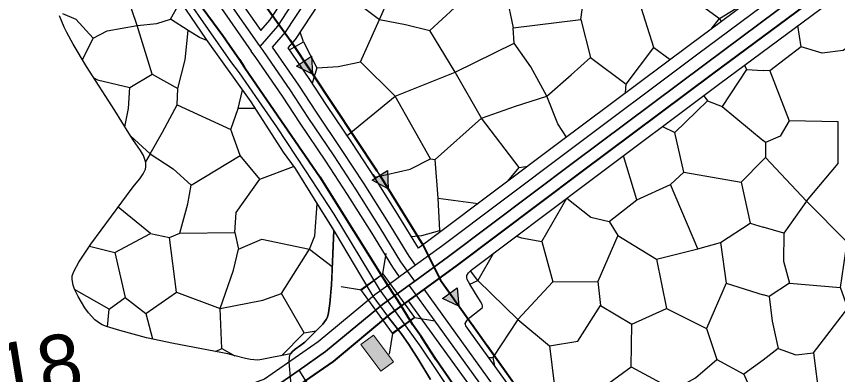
# Model space of a CAD drawing. Extents: x -64005 to -55000, y -89025 to -80000.
# Drawn here: x -62111 to -61273, y -80924 to -80558 of the extents above; entities that cross this region are included whole.
import ezdxf
from ezdxf.enums import TextEntityAlignment as Align

# ---------------------------------------------------------------- set-up
doc = ezdxf.new("R2010")
doc.units = 0
doc.header["$LTSCALE"] = 32
for name, pattern in [('DASH_DOUBLE_DOT', [9.2, 5, -1.2, 0.3, -1.2, 0.3, -1.2]), ('DOT_DASHED', [7.7, 5, -1.2, 0.3, -1.2]), ('LONG_DASHED', [7.5, 6, -1.5])]:
    doc.linetypes.add(name, pattern=pattern)
for name, color, linetype, lineweight in [('18', 7, 'Continuous', 25), ('19', 7, 'Continuous', 25), ('20', 7, 'Continuous', 25), ('3', 7, 'Continuous', 25), ('39', 7, 'LONG_DASHED', 25), ('5', 7, 'Continuous', 40), ('53', 7, 'DASH_DOUBLE_DOT', 25), ('63', 7, 'DASH_DOUBLE_DOT', 25), ('7', 7, 'Continuous', 13), ('8', 7, 'Continuous', 25)]:
    doc.layers.add(name, color=color, linetype=linetype, lineweight=lineweight)
doc.layers.add('30', color=7, linetype='Continuous')

msp = doc.modelspace()

# ---------------------------------------------------------------- hatches: boundary and pattern name
at = {"layer": '18'}
for points in [[(-61809.8, -80598.75), (-61808.66, -80617.22), (-61825.22, -80608.97)], [(-61732.29, -80715.66), (-61731.68, -80734.14), (-61747.99, -80725.43)], [(-61661.08, -80835.3), (-61659.3, -80853.71), (-61676.13, -80846.05)]]:
    msp.add_hatch(color=256, dxfattribs=at).paths.add_polyline_path(points)
at = {"layer": '7'}
msp.add_hatch(color=256, dxfattribs=at).paths.add_polyline_path([(-61726.19, -80910.68), (-61746.45, -80883.37), (-61759.3, -80892.9), (-61739.05, -80920.21)])

# ---------------------------------------------------------------- linework, layer by layer
at = {"layer": '18'}
for p, q in [((-61781.03, -80658.89), (-61740.16, -80720.55)), ((-61630.24, -80894.41), (-61587.26, -80954.62))]:
    msp.add_line(p, q, dxfattribs=at)
at = {"layer": '18', "linetype": 'DOT_DASHED', "lineweight": 40}
msp.add_lwpolyline([(-62130.95, -80220.51), (-62065.47, -80292.93), (-61983.02, -80390.5), (-61893.31, -80496.28), (-61831.59, -80582.62), (-61739.82, -80721.06), (-61696.2, -80791.15), (-61678.11, -80827.36), (-61574.26, -80972.82), (-61474.5, -81109.75), (-61380.53, -81246.93), (-61313.48, -81342.67)], dxfattribs=at)
at = {"layer": '18'}
for points in [[(-61859.79, -80543.17), (-61831.59, -80582.62), (-61817.51, -80603.86)], [(-61705.26, -80776.6), (-61696.2, -80791.15), (-61678.11, -80827.36), (-61668.6, -80840.67)]]:
    msp.add_lwpolyline(points, dxfattribs=at)
for points in [[(-61809.8, -80598.75), (-61808.66, -80617.22), (-61825.22, -80608.97)], [(-61732.29, -80715.66), (-61731.68, -80734.14), (-61747.99, -80725.43)], [(-61661.08, -80835.3), (-61659.3, -80853.71), (-61676.13, -80846.05)]]:
    msp.add_lwpolyline(points, close=True, dxfattribs=at)
for centre in [(-61794.84, -80638.05), (-61718.47, -80755.37), (-61644.77, -80874.06)]:
    msp.add_circle(centre, 0.5, dxfattribs=at)
at = {"layer": '19'}
for p, q in [((-61402.12, -80571.2), (-61393.6, -80560.36)), ((-61393.6, -80560.36), (-61391.78, -80563.51)), ((-62043.53, -80602.67), (-62032.51, -80580.63)), ((-61460.64, -80590.12), (-61443.7, -80602.22)), ((-61489.25, -80636.31), (-61488.59, -80627.42)), ((-61773.54, -80679.96), (-61724.57, -80639.78)), ((-61867.15, -80652.36), (-61884.61, -80652.12)), ((-61974.45, -80698.38), (-61979.12, -80706.61)), ((-61346.47, -80702.34), (-61348.89, -80704.76)), ((-61862.61, -80724.38), (-61828.26, -80711.29)), ((-61597.75, -80712.48), (-61589.06, -80711.09)), ((-61745.21, -80722.95), (-61744.82, -80722.18)), ((-61680.53, -80743.76), (-61639.59, -80749.05)), ((-61677.97, -80777.88), (-61678.78, -80776.81)), ((-61648.31, -80831.34), (-61640.06, -80827.78)), ((-62016.38, -80856.84), (-62051.49, -80836.9)), ((-61978.76, -80861.25), (-61972.03, -80887.33)), ((-61817.14, -80881.08), (-61805.12, -80879.09)), ((-61901.25, -80896.94), (-61888.17, -80904.37)), ((-61629.09, -80906.37), (-61624.64, -80906.19))]:
    msp.add_line(p, q, dxfattribs=at)
for points in [[(-60656, -80058.71), (-60736.07, -80110.4), (-60829.56, -80171.35), (-60995.24, -80276.06), (-61089.62, -80335.36), (-61146.26, -80375.39), (-61228.6, -80439.09), (-61304.45, -80498.56), (-61423.15, -80586.84), (-61557.42, -80687.33), (-61684.72, -80782.95), (-61700.7, -80794.56)], [(-62451.82, -80075.02), (-62421.27, -80077.57), (-62404.53, -80079.71), (-62388.83, -80081.51), (-62362.81, -80088.69), (-62340.82, -80101.26), (-62317.5, -80116.52), (-62297.31, -80135.37), (-62269.04, -80160.92), (-62205.35, -80231.41), (-62145.24, -80301.62), (-62103.48, -80350.87), (-62044.29, -80419.34), (-61992.7, -80480.96), (-61964.43, -80514.17), (-61943.35, -80543.35), (-61917.33, -80581.95), (-61871.66, -80645.3), (-61838.76, -80696.8), (-61826.6, -80713.58), (-61806.97, -80744.83), (-61787.11, -80776.61)], [(-61833.68, -80590.41), (-61826.2, -80581.78), (-61793.4, -80531.79), (-61776.09, -80505.2), (-61766.99, -80481.49), (-61758.32, -80447.6), (-61747.16, -80415.22), (-61715.39, -80338.74), (-61687.94, -80245.45), (-61669.19, -80193.12), (-61660.33, -80161.85), (-61656.91, -80133.65)], [(-61646.85, -80817.07), (-61527.41, -80727.33), (-61393.27, -80626.92), (-61274.09, -80538.32), (-61197.88, -80478.53), (-61116.54, -80415.58), (-61061.89, -80377), (-60968.59, -80318.37), (-60881, -80263.01)], [(-61784.83, -80525.57), (-61770.63, -80538.44), (-61740.44, -80561.54), (-61717.36, -80509.13), (-61740.88, -80470.05)], [(-61740.44, -80561.54), (-61713.8, -80566.43), (-61688.94, -80572.65), (-61651.21, -80537.55), (-61680.06, -80497.13), (-61717.36, -80509.13)], [(-61611.26, -80535.78), (-61604.16, -80569.97), (-61534.9, -80561.53), (-61530.46, -80529.1), (-61532.69, -80496.25)], [(-62064.02, -80555.31), (-62050.27, -80561.1), (-62032.51, -80580.63), (-62018.31, -80573.09), (-61987.69, -80567.76), (-62004.1, -80519.35)], [(-61444.34, -80523.32), (-61393.6, -80560.36), (-61357.4, -80537.94)], [(-61534.9, -80561.53), (-61524.98, -80600.32), (-61488.59, -80627.42), (-61460.64, -80590.12), (-61479.39, -80529.55)], [(-61987.69, -80567.76), (-61967.71, -80565.54), (-61953.5, -80561.1), (-61943.55, -80543.08)], [(-62053.84, -80822.93), (-62053.44, -80821.13), (-62052.41, -80818.56), (-62047.09, -80809.03), (-62043.22, -80802.74), (-62034.88, -80790.5), (-61992.81, -80733.51), (-61990.37, -80730.33), (-61985.12, -80723.91), (-61981.65, -80719.03), (-61979.32, -80714.09), (-61978.79, -80711.6), (-61978.86, -80707.88), (-61979.38, -80705.37), (-61981.34, -80700.3), (-61984.24, -80695.2), (-61991.32, -80684.98), (-61996.32, -80677.41), (-62010.47, -80654.39), (-62039.47, -80609.48), (-62053.09, -80586.61), (-62059.41, -80574.85), (-62062.15, -80569.23), (-62066.96, -80557.72)], [(-61916.53, -80583.06), (-61924.2, -80579.75), (-61935.75, -80572.65), (-61953.5, -80561.1)], [(-61804.48, -80610.7), (-61782.7, -80609.39), (-61759.79, -80604.54), (-61740.44, -80561.54)], [(-61243.06, -80576.2), (-61267.46, -80593.07), (-61288.78, -80595.72), (-61310.08, -80589.51), (-61313.46, -80567.59)], [(-62032, -80621.05), (-62028.17, -80623.05), (-61995.14, -80630.98), (-61972.25, -80617.32), (-61987.69, -80567.76)], [(-61972.25, -80617.32), (-61946.27, -80631.85), (-61938.78, -80602.77), (-61935.75, -80572.65)], [(-61832.36, -80592.34), (-61818.11, -80584.2), (-61821.43, -80574.51)], [(-61759.79, -80604.54), (-61724.57, -80639.78), (-61663.36, -80615.11), (-61688.94, -80572.65)], [(-61663.36, -80615.11), (-61603.03, -80585.59), (-61604.16, -80569.97)], [(-61818.11, -80584.2), (-61804.48, -80610.7), (-61808.98, -80626.67)], [(-61700.7, -80794.56), (-61720.58, -80762), (-61745.66, -80722.24), (-61768.09, -80688.05), (-61794.28, -80649.15), (-61812.33, -80621.54), (-61833.68, -80590.41)], [(-61636.51, -80662.25), (-61601.72, -80649.93), (-61569.57, -80639.78), (-61585.86, -80609.83), (-61603.03, -80585.59)], [(-61310.08, -80589.51), (-61342.08, -80613.79), (-61348.89, -80613.37)], [(-61569.57, -80639.78), (-61544.9, -80617.75), (-61524.98, -80600.32)], [(-61368.01, -80608.14), (-61366.09, -80612.32), (-61348.89, -80613.37)], [(-61688.46, -80703.67), (-61683.62, -80704.11), (-61636.51, -80662.25), (-61663.36, -80615.11)], [(-61366.09, -80612.32), (-61390.94, -80650.08), (-61348.89, -80684.91)], [(-61342.08, -80613.79), (-61322.26, -80664.9), (-61331.5, -80680.32), (-61346.47, -80686.92), (-61348.89, -80684.91)], [(-62000.19, -80671.11), (-61996.47, -80652.12), (-61995.14, -80630.98)], [(-61994.23, -80680.58), (-61974.45, -80698.38), (-61961.68, -80676.36), (-61946.7, -80648.6), (-61946.27, -80631.85)], [(-61946.7, -80648.6), (-61892.1, -80673.71), (-61884.61, -80652.12), (-61880.22, -80633.42)], [(-61747.38, -80719.62), (-61744.82, -80722.18), (-61709.16, -80714.25), (-61688.46, -80703.67), (-61724.57, -80639.78)], [(-61549.51, -80681.41), (-61558.57, -80667.98), (-61569.57, -80639.78)], [(-61409.64, -80639.17), (-61405.59, -80644.29), (-61390.94, -80650.08)], [(-61451.53, -80670.53), (-61439.23, -80676.79), (-61405.59, -80644.29)], [(-61609.36, -80726.35), (-61597.75, -80712.48), (-61636.51, -80662.25)], [(-61304.65, -80746.85), (-61272.5, -80708.51), (-61272.5, -80665.78), (-61322.26, -80664.9)], [(-61974.45, -80698.38), (-61951.11, -80713.8), (-61932.61, -80730.55), (-61882.42, -80700.14), (-61892.1, -80673.71)], [(-61477.98, -80745.52), (-61443.62, -80729.66), (-61429.98, -80717.33), (-61439.23, -80676.79)], [(-61346.47, -80686.92), (-61346.47, -80702.34), (-61304.65, -80746.85), (-61327.98, -80779.45), (-61348.89, -80773.26)], [(-61944.06, -80779.45), (-61888.14, -80778.58), (-61886.82, -80758.31), (-61862.61, -80724.38), (-61882.42, -80700.14)], [(-61549.29, -80743.77), (-61524.65, -80763.15), (-61506.16, -80767.56), (-61477.98, -80745.52), (-61491.61, -80700.53)], [(-61707.82, -80782.9), (-61697.28, -80781.66), (-61678.78, -80776.81), (-61680.53, -80743.76), (-61683.62, -80704.11)], [(-61429.98, -80717.33), (-61371.45, -80727.47), (-61348.89, -80704.76)], [(-61304.65, -80746.85), (-61263.24, -80788.7), (-61243.88, -80781.65), (-61224.5, -80772.84), (-61216.58, -80726.57), (-61200.2, -80732.34)], [(-61974.01, -80779.89), (-61954.63, -80783.86), (-61944.06, -80779.45), (-61936.14, -80749.49), (-61932.61, -80730.55)], [(-61506.16, -80767.56), (-61497.35, -80781.66), (-61457.73, -80805.89), (-61415.45, -80795.31), (-61443.62, -80729.66)], [(-61371.45, -80727.47), (-61362.2, -80769.32), (-61348.89, -80773.26)], [(-61888.14, -80778.58), (-61884.19, -80795.76), (-61860.4, -80785.61), (-61811.97, -80795.76), (-61806.25, -80782.09), (-61804.12, -80749.38)], [(-61600.6, -80782.32), (-61595.54, -80784.3), (-61574.85, -80787.82), (-61549.35, -80743.81)], [(-62036.45, -80792.8), (-62010.55, -80799.27), (-61974.01, -80779.89), (-62007.03, -80752.78)], [(-61787.11, -80776.61), (-61789.31, -80831.95), (-61790.95, -80851.17), (-61792.3, -80860.75), (-61793.5, -80864.93), (-61794.79, -80867.56), (-61798.29, -80872.21), (-61816.5, -80890.55), (-61820.54, -80893.77), (-61826.53, -80897.77), (-61829.15, -80899.95), (-61831.25, -80902.57)], [(-61415.45, -80795.31), (-61392.58, -80789), (-61362.2, -80769.32)], [(-62010.55, -80799.27), (-61999.89, -80844.96), (-61978.76, -80861.25), (-61947.48, -80839.66), (-61954.63, -80783.86)], [(-61497.35, -80781.66), (-61517.64, -80828.65), (-61515, -80853.32), (-61482.85, -80872.27), (-61447.62, -80856.4)], [(-61327.98, -80779.45), (-61328.29, -80807.95), (-61322.13, -80830.42), (-61342.82, -80844.07), (-61348.89, -80842.19)], [(-61574.85, -80787.82), (-61563.43, -80829.09), (-61517.64, -80828.65)], [(-61392.58, -80789), (-61386.85, -80830.42), (-61348.89, -80842.19)], [(-61322.13, -80830.42), (-61270.17, -80834.82), (-61263.24, -80788.7)], [(-61947.48, -80839.66), (-61903.01, -80856.4), (-61889.35, -80817.2), (-61884.19, -80795.76)], [(-61903.01, -80856.4), (-61859.42, -80847.6), (-61840.48, -80840.99), (-61811.97, -80795.76), (-61788.57, -80813.46)], [(-61623.95, -80799.86), (-61640.06, -80827.78), (-61647.61, -80817.84)], [(-61457.73, -80805.89), (-61447.62, -80856.4), (-61406.68, -80876.68)], [(-61649.07, -80878.74), (-61652.31, -80873.93), (-61652.81, -80872.58), (-61652.85, -80871.58), (-61652.03, -80869.78), (-61650.56, -80867.82), (-61648.11, -80865.54), (-61638.86, -80858.03), (-61635.73, -80855.56), (-61635.33, -80855), (-61635.18, -80853.6), (-61635.68, -80852.01), (-61637.52, -80849.07), (-61643.54, -80839.26), (-61648.27, -80831.42), (-61650.88, -80826.52), (-61651.46, -80824.61), (-61651.14, -80822.65), (-61649.74, -80819.99), (-61646.85, -80817.07)], [(-61831.25, -80902.57), (-61860.55, -80908.4), (-61864.39, -80908.88), (-61872.11, -80908.41), (-61877.26, -80907.36), (-61887.58, -80904.51), (-61895.31, -80902.63), (-61950.6, -80892.05), (-61978.05, -80886.01), (-62005.43, -80878.83), (-62019.1, -80874.66), (-62023.43, -80872.88), (-62026.1, -80871.37), (-62030.98, -80867.67), (-62037.36, -80860.71), (-62041.13, -80855.41), (-62048.03, -80843.98), (-62051.7, -80836.47), (-62053.03, -80832.54), (-62054.03, -80826.69), (-62053.84, -80822.93)], [(-61640.06, -80827.78), (-61599.1, -80867.42), (-61563.43, -80829.09)], [(-61386.85, -80830.42), (-61406.68, -80876.68), (-61396.1, -80908.4), (-61368.8, -80923.37)], [(-61333.57, -80896.94), (-61315.52, -80903.56), (-61297.46, -80901.35), (-61262.68, -80855.97), (-61270.17, -80834.82)], [(-61840.47, -80904.4), (-61817.14, -80881.08), (-61840.48, -80840.99)], [(-61342.82, -80844.07), (-61339.74, -80869.19), (-61333.57, -80896.94), (-61348.89, -80908.9)], [(-62017.87, -80875.03), (-62016.38, -80856.84), (-61999.89, -80844.96)], [(-61907.76, -80900.25), (-61901.25, -80896.94), (-61903.01, -80856.4)], [(-61599.1, -80867.42), (-61566.97, -80894.3), (-61537.9, -80889.46), (-61515, -80853.32)], [(-61599.1, -80867.42), (-61624.64, -80906.19), (-61623.12, -80914.63)], [(-61566.97, -80894.3), (-61562.12, -80933.07), (-61543.18, -80938.8), (-61518.97, -80941.44), (-61483.73, -80915.88), (-61482.85, -80872.27)], [(-61242.06, -81017.41), (-61321.92, -81046.31), (-61359.08, -81060.4), (-61435.11, -81088.93), (-61484.62, -81106.14), (-61649.07, -80878.74)], [(-61297.46, -80901.35), (-61291.74, -80947.17), (-61316.41, -80983.74), (-61334.9, -80974.48), (-61348.89, -80960.8)], [(-61483.73, -80915.88), (-61440.15, -80939.24), (-61418.13, -80926.91), (-61396.1, -80908.4)], [(-61348.89, -80908.9), (-61368.8, -80923.37), (-61354.72, -80955.11), (-61348.89, -80960.8)]]:
    msp.add_lwpolyline(points, dxfattribs=at)
at = {"layer": '20'}
for points in [[(-61779.68, -80833.91), (-61758.73, -80837.24), (-61737.08, -80821.06), (-61733.76, -80800.11)], [(-61730.22, -80902.84), (-61726.9, -80881.89), (-61704.76, -80865.56), (-61683.81, -80868.89)]]:
    msp.add_lwpolyline(points, dxfattribs=at)
at = {"layer": '3'}
msp.add_line((-61787.11, -80776.62), (-61785.55, -80779.12), dxfattribs=at)
for points in [[(-62451.82, -80075.02), (-62430.49, -80076.8), (-62421.27, -80077.57), (-62404.53, -80079.71), (-62388.83, -80081.51), (-62362.81, -80088.69), (-62340.82, -80101.26), (-62317.5, -80116.52), (-62297.31, -80135.37), (-62269.04, -80160.92), (-62205.35, -80231.41), (-62145.24, -80301.62), (-62103.48, -80350.87), (-62044.29, -80419.34), (-61992.7, -80480.96), (-61964.43, -80514.17), (-61943.35, -80543.35), (-61917.33, -80581.95), (-61871.66, -80645.3), (-61838.76, -80696.8), (-61826.6, -80713.58), (-61806.97, -80744.83), (-61787.11, -80776.62)], [(-62451.82, -80075.02), (-62430.49, -80076.8), (-62421.27, -80077.57), (-62404.53, -80079.71), (-62388.83, -80081.51), (-62362.81, -80088.69), (-62340.82, -80101.26), (-62317.5, -80116.52), (-62297.31, -80135.37), (-62269.04, -80160.92), (-62205.35, -80231.41), (-62145.24, -80301.62), (-62103.48, -80350.87), (-62044.29, -80419.34), (-61992.7, -80480.96), (-61964.43, -80514.17), (-61943.35, -80543.35), (-61917.33, -80581.95), (-61871.66, -80645.3), (-61838.76, -80696.8), (-61826.6, -80713.58), (-61806.97, -80744.83), (-61785.55, -80779.12)], [(-61718.15, -80853.54), (-61731.95, -80832.71), (-61801.25, -80722.01), (-61873.48, -80617.14), (-61878.34, -80609.64), (-61883.3, -80602.21), (-61893.45, -80587.5), (-61900.37, -80577.8), (-61909.74, -80564.96), (-61922.38, -80547.94), (-61939.3, -80525.29), (-61968.41, -80485.98), (-61978.21, -80472.95), (-61991.48, -80455.75), (-61999.2, -80446.04), (-62008.19, -80435.06), (-62018.7, -80422.72), (-62055.88, -80380.18), (-62093.14, -80337.73), (-62167.81, -80252.93)], [(-61785.55, -80779.12), (-61759.96, -80822.64), (-61747.15, -80843.68), (-61732.18, -80864.03)], [(-61785.55, -80779.12), (-61759.96, -80822.64), (-61747.15, -80843.68), (-61732.18, -80864.03)], [(-61646.35, -80961.3), (-61682.49, -80908.47), (-61687.63, -80900.68), (-61697.89, -80884.65), (-61706.3, -80872.85), (-61718.15, -80853.54)], [(-61688.25, -80928.61), (-61700.21, -80908.86), (-61710.33, -80893.05), (-61718.34, -80881.81), (-61732.18, -80864.03)], [(-61732.18, -80864.03), (-61718.34, -80881.81), (-61710.33, -80893.05), (-61700.21, -80908.86), (-61688.25, -80928.61)]]:
    msp.add_lwpolyline(points, dxfattribs=at)
at = {"layer": '3', "lineweight": 40}
for points in [[(-62167.81, -80252.93), (-62093.14, -80337.73), (-62055.88, -80380.18), (-62018.7, -80422.72), (-62008.19, -80435.06), (-61999.2, -80446.04), (-61991.48, -80455.75), (-61978.21, -80472.95), (-61968.41, -80485.98), (-61939.3, -80525.29), (-61922.38, -80547.94), (-61909.74, -80564.96), (-61900.37, -80577.8), (-61893.45, -80587.5), (-61883.3, -80602.21), (-61878.34, -80609.64), (-61873.48, -80617.14), (-61801.25, -80722.01), (-61731.95, -80832.71), (-61718.15, -80853.54)], [(-61646.35, -80961.3), (-61682.49, -80908.47), (-61687.63, -80900.68), (-61697.89, -80884.65), (-61706.3, -80872.85), (-61718.15, -80853.54)]]:
    msp.add_lwpolyline(points, dxfattribs=at)
at = {"layer": '39'}
for p, q in [((-61862.25, -80589.03), (-61863.05, -80587.99)), ((-61493.05, -81132.9), (-61710.31, -80832.45))]:
    msp.add_line(p, q, dxfattribs=at)
at = {"layer": '39', "lineweight": 35}
msp.add_line((-61704.48, -80828.21), (-61710.31, -80832.45), dxfattribs=at)
at = {"layer": '39'}
for points in [[(-61862.25, -80589.03), (-61844.18, -80568.19), (-61812.24, -80519.48), (-61796.25, -80494.92), (-61788.46, -80474.65), (-61779.89, -80441.14), (-61768.2, -80407.23), (-61736.63, -80331.23), (-61709.34, -80238.48), (-61690.63, -80186.25), (-61682.45, -80157.41), (-61679.72, -80134.8), (-61684.4, -80114.15), (-61694.93, -80084.14), (-61700.38, -80074.79), (-61706.62, -80067), (-61712.07, -80064.66), (-61716.75, -80060.76), (-61724.15, -80047.51), (-61726.88, -80028.81), (-61728.64, -80000)], [(-62570.89, -80039.27), (-62499.53, -80036.52), (-62451.16, -80036.86), (-62410.45, -80038.95), (-62384.35, -80042.08), (-62366.94, -80045.2), (-62353.02, -80049.38), (-62327.28, -80061.21), (-62286.57, -80092.87), (-62247.25, -80128.69), (-62201.66, -80178.45), (-62163.72, -80221.25), (-62103.87, -80290.49), (-62016.18, -80394.87), (-61916.3, -80511.79), (-61863.05, -80587.99)], [(-61704.48, -80828.21), (-61718.52, -80808.55), (-61739.7, -80773.86), (-61764.59, -80734.41), (-61786.83, -80700.52), (-61813.03, -80661.6), (-61831.03, -80634.07), (-61859.22, -80592.96), (-61862.25, -80589.03)], [(-61929.55, -81539.6), (-61936.35, -81405.86), (-61945.71, -81304.67), (-61940.72, -81254.71), (-61926.98, -81224.1), (-61912.62, -81208.49), (-61888.9, -81202.87), (-61847.07, -81203.49), (-61827.14, -81202.57), (-61809.66, -81195.07), (-61794.67, -81181.96), (-61790.3, -81170.09), (-61787.8, -81160.1), (-61794.67, -81071.41), (-61803.41, -80963.35), (-61811.53, -80936.5), (-61822.44, -80919.01)]]:
    msp.add_lwpolyline(points, dxfattribs=at)
at = {"layer": '39', "lineweight": 35}
for points in [[(-60629.14, -80070.38), (-60722.51, -80131.4), (-60816.06, -80192.39), (-60981.92, -80297.21), (-61075.75, -80356.18), (-61131.4, -80395.49), (-61213.24, -80458.81), (-61289.27, -80518.44), (-61408.21, -80606.88), (-61542.42, -80707.33), (-61669.86, -80803.07), (-61704.48, -80828.21)], [(-61710.31, -80832.45), (-61737.52, -80852.21), (-61795.35, -80900.25), (-61822.44, -80919.01)], [(-62457.8, -81018.1), (-62428.52, -81019.18), (-62255.11, -81014.27), (-62235.83, -81013.72), (-62121.25, -80996.24), (-61989.22, -80976.57), (-61905.56, -80959.21), (-61852.08, -80939.55), (-61822.44, -80919.01)]]:
    msp.add_lwpolyline(points, dxfattribs=at)
at = {"layer": '5', "lineweight": 25}
msp.add_line((-61703.65, -80812.16), (-61719.84, -80823.92), dxfattribs=at)
at = {"layer": '5'}
msp.add_line((-61694.89, -80836.7), (-61711.07, -80848.45), dxfattribs=at)
at = {"layer": '5', "lineweight": 25}
for points in [[(-60548.6, -80000), (-60563.64, -80012.95), (-60729.29, -80120.9), (-60822.81, -80181.87), (-60988.58, -80286.64), (-61082.68, -80345.77), (-61138.83, -80385.44), (-61220.92, -80448.95), (-61296.86, -80508.5), (-61415.68, -80596.86), (-61549.92, -80697.33), (-61677.29, -80793.01), (-61703.65, -80812.16)], [(-61719.84, -80823.92), (-61731.95, -80832.71), (-61745.19, -80842.33), (-61747.6, -80844.33), (-61802.92, -80890.28), (-61857.89, -80928.37), (-61909, -80947.16), (-61991.41, -80964.26), (-62123.11, -80983.88), (-62236.95, -81001.25), (-62428.46, -81006.67), (-62443.22, -81006.13)]]:
    msp.add_lwpolyline(points, dxfattribs=at)
at = {"layer": '5'}
for points in [[(-60648.75, -80099), (-60715.73, -80141.9), (-60809.31, -80202.91), (-60975.25, -80307.79), (-61068.82, -80366.59), (-61123.97, -80405.53), (-61205.56, -80468.67), (-61281.68, -80528.38), (-61400.74, -80616.9), (-61534.91, -80717.33), (-61662.43, -80813.13), (-61694.89, -80836.7)], [(-61711.07, -80848.45), (-61729.85, -80862.09), (-61732.18, -80864.03), (-61787.78, -80910.22), (-61807.36, -80923.78), (-61821.74, -80933.75)]]:
    msp.add_lwpolyline(points, dxfattribs=at)
at = {"layer": '53'}
msp.add_lwpolyline([(-61158.37, -81694.12), (-61208.21, -81612.26), (-61256.98, -81543.39), (-61306.17, -81468.06), (-61336.39, -81419.48), (-61359.63, -81381.08), (-61446.4, -81260), (-61536.28, -81133.53), (-61591.17, -81054.02), (-61643.69, -80976.53), (-61697.92, -80895.67), (-61740.47, -80836.38), (-61786.75, -80759.9), (-61815.53, -80715.9), (-61845.24, -80670.86), (-61863.43, -80644.37), (-61883.23, -80616.04), (-61892.2, -80604.35), (-61940.32, -80535.23), (-61993.16, -80465.96), (-62084.57, -80359.35), (-62134.18, -80302.16)], dxfattribs=at)
at = {"layer": '63'}
msp.add_lwpolyline([(-61759.38, -80836.96), (-61737.08, -80821.06), (-61704.76, -80865.56), (-61727.06, -80881.46)], close=True, dxfattribs=at)
at = {"layer": '7', "lineweight": 25}
msp.add_lwpolyline([(-61829.02, -80938.79), (-61831, -80930.49), (-61832.55, -80910.82), (-61832.27, -80906.09), (-61831.79, -80903.79), (-61831.12, -80902.41), (-61829.15, -80899.95), (-61826.53, -80897.77), (-61820.54, -80893.77), (-61816.5, -80890.55), (-61798.29, -80872.21), (-61794.79, -80867.56), (-61793.5, -80864.93), (-61792.3, -80860.75), (-61790.95, -80851.17), (-61789.31, -80831.95), (-61788.77, -80818.34), (-61788.03, -80800.21), (-61787.11, -80776.62)], dxfattribs=at)
at = {"layer": '7'}
msp.add_lwpolyline([(-61726.19, -80910.68), (-61746.45, -80883.37), (-61759.3, -80892.9), (-61739.05, -80920.21)], close=True, dxfattribs=at)
at = {"layer": '8'}
msp.add_line((-61489.31, -81121.01), (-61694.89, -80836.7), dxfattribs=at)
for points in [[(-62349.49, -80040), (-62322.05, -80052.61), (-62280.12, -80085.22), (-62240.18, -80121.6), (-62194.22, -80171.76), (-62156.19, -80214.66), (-62096.26, -80284), (-62008.55, -80388.41), (-61908.38, -80505.66), (-61861.43, -80572.84)], [(-61849.44, -80589.54), (-61836.19, -80574.23), (-61803.86, -80524.95), (-61787.29, -80499.49), (-61778.92, -80477.69), (-61770.3, -80444.01), (-61758.85, -80410.78), (-61727.19, -80334.57), (-61699.83, -80241.57), (-61681.1, -80189.3), (-61672.62, -80159.39), (-61669.58, -80134.28), (-61669.7, -80133.76)], [(-61703.65, -80812.16), (-61710.17, -80803.03), (-61731.2, -80768.59), (-61756.17, -80729), (-61778.5, -80694.97), (-61804.7, -80656.06), (-61822.72, -80628.5), (-61849.44, -80589.54)]]:
    msp.add_lwpolyline(points, dxfattribs=at)
at = {"layer": '8', "linetype": 'LONG_DASHED'}
for points in [[(-62356.52, -80058.78), (-62332.51, -80069.81), (-62293.02, -80100.52), (-62254.32, -80135.79), (-62209.09, -80185.14), (-62171.25, -80227.84), (-62111.48, -80296.98), (-62023.81, -80401.33), (-61924.22, -80517.92), (-61871.25, -80593.72)], [(-61861.43, -80572.84), (-61852.17, -80562.15), (-61820.61, -80514.01), (-61805.21, -80490.35), (-61798, -80471.61), (-61789.48, -80438.27), (-61777.55, -80403.68), (-61746.07, -80327.9), (-61718.86, -80235.38), (-61700.16, -80183.2), (-61692.28, -80155.43), (-61689.86, -80135.33), (-61690.05, -80134.51)], [(-61719.84, -80823.92), (-61726.87, -80814.08), (-61748.21, -80779.14), (-61773, -80739.83), (-61795.16, -80706.06), (-61821.36, -80667.13), (-61839.34, -80639.63), (-61866.43, -80600.13), (-61871.25, -80593.72)], [(-61711.07, -80848.45), (-61499.44, -81141.14), (-61369.32, -81330.93), (-61282.87, -81451.47), (-61159.58, -81636.84), (-61005.49, -81886.15), (-60861.01, -82128.03), (-60810.74, -82214.1)]]:
    msp.add_lwpolyline(points, dxfattribs=at)

# ---------------------------------------------------------------- texts
at = {"layer": '30'}
msp.add_text('118', height=60, rotation=9.372, dxfattribs=at).set_placement((-62106.09, -80949.77), align=Align.CENTER)

doc.saveas('drawing.dxf')
